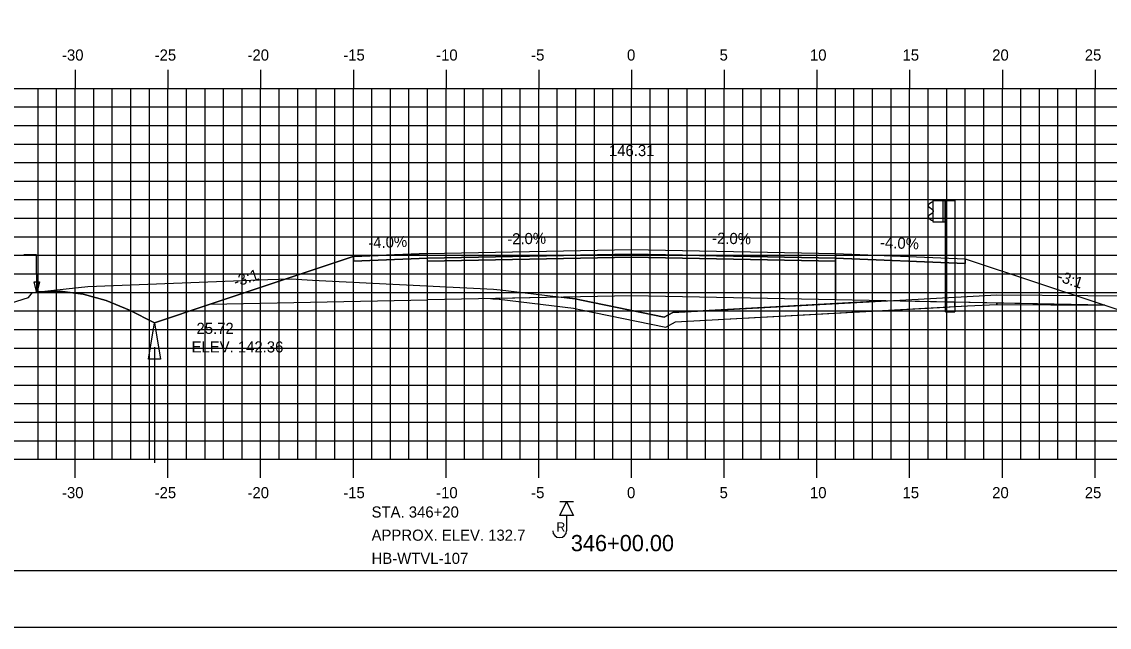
# Model space of a CAD drawing. Extents: x 1143863 to 1144033, y 608981 to 609091.
# Drawn here: x 1143913.7 to 1143972.4, y 608981.3 to 609013.9 of the extents above; entities that cross this region are included whole.
import ezdxf

# ---------------------------------------------------------------- set-up
doc = ezdxf.new("R2010")
doc.units = 0
for name, color, linetype in [('ANNOTATION', 7, 'Continuous'), ('BORDER', 7, 'Continuous'), ('D_Drainage_Ditch_Line', 7, 'Continuous'), ('D_Guardrail_Beam_Rt', 7, 'Continuous'), ('D_Guardrail_ConcBarrier', 7, 'Continuous'), ('D_Roadway_Centerline', 7, 'Continuous'), ('D_Roadway_Centerline_Text', 7, 'Continuous'), ('D_Roadway_Edge_Shoulder', 7, 'Continuous'), ('D_Roadway_Edge_TW', 7, 'Continuous'), ('D_Roadway_Pavement', 7, 'Continuous'), ('D_Roadway_SlopeLines', 7, 'Continuous'), ('D_Roadway_SubGrade', 7, 'Continuous'), ('D_Text_Standard', 7, 'Continuous'), ('H_V ANNOTATION', 7, 'Continuous'), ('MAJOR', 7, 'Continuous'), ('MINOR', 7, 'Continuous'), ('PLOT BOUNDARY', 7, 'Continuous'), ('ROCKS', 7, 'Continuous'), ('S_Roadway_Centerline', 7, 'Continuous'), ('SHADING', 7, 'Continuous')]:
    doc.layers.add(name, color=color, linetype=linetype)

msp = doc.modelspace()

# ---------------------------------------------------------------- linework, layer by layer
msp.add_lwpolyline([(1143914.516, 608999.356), (1143915.766, 608999.394), (1143917.016, 608999.242), (1143918.266, 608998.902), (1143919.516, 608998.371), (1143920.868, 608997.695), (1143923.868, 608998.695), (1143931.592, 609001.27), (1143931.593, 609001.27), (1143935.593, 609001.43), (1143946.593, 609001.65), (1143957.593, 609001.43), (1143964.593, 609001.15), (1143972.125, 608998.639), (1143975.125, 608997.639), (1143975.57, 608997.862), (1143976.82, 608998.408), (1143978.07, 608998.795), (1143979.32, 608999.024), (1143980.57, 608999.095)])
at = {"layer": 'BORDER'}
msp.add_lwpolyline([(1143871.593, 608984.335), (1144031.593, 608984.335), (1144031.593, 609089.335), (1143871.593, 609089.335)], close=True, dxfattribs=at)
at = {"layer": 'D_Drainage_Ditch_Line'}
msp.add_line((1143920.868, 608996.383), (1143920.868, 608990.14), dxfattribs=at)
msp.add_lwpolyline([(1143921.196, 608995.727), (1143920.54, 608995.727), (1143920.868, 608997.695)], close=True, dxfattribs=at)
at = {"layer": 'D_Guardrail_Beam_Rt'}
for p, q in [((1143962.777, 609004.186), (1143962.634, 609004.086)), ((1143962.867, 609004.207), (1143962.793, 609004.193)), ((1143962.634, 609003.943), (1143962.829, 609003.807)), ((1143962.829, 609003.608), (1143962.634, 609003.472)), ((1143962.863, 609003.742), (1143962.863, 609003.672)), ((1143962.634, 609003.329), (1143962.777, 609003.229)), ((1143962.793, 609003.222), (1143962.867, 609003.207))]:
    msp.add_line(p, q, dxfattribs=at)
for centre, major_axis, start_param, end_param in [((1143962.684, 609004.014), (-0.0877, 0), 5.323254, 7.243116), ((1143962.801, 609004.152), (-0.0417, 0), 4.907132, 5.323254), ((1143962.684, 609003.4), (-0.0877, 0), 5.323254, 7.243116), ((1143962.784, 609003.742), (0.0789, 0), 0, 0.959931), ((1143962.784, 609003.672), (0.0789, 0), 5.323254, 6.283185), ((1143962.801, 609003.263), (-0.0417, 0), 0.959931, 1.376053)]:
    msp.add_ellipse(centre, major_axis=major_axis, ratio=0.995501, start_param=start_param, end_param=end_param, dxfattribs=at)
at = {"layer": 'D_Guardrail_ConcBarrier'}
for p, q in [((1143962.867, 609004.291), (1143963.555, 609004.291)), ((1143962.867, 609003.124), (1143962.867, 609004.291)), ((1143963.388, 609004.291), (1143963.388, 609003.124)), ((1143963.492, 609004.291), (1143963.492, 609003.124)), ((1143963.555, 609004.291), (1143964.026, 609004.291)), ((1143963.555, 609004.291), (1143963.555, 609003.124)), ((1143964.026, 609004.291), (1143964.026, 608998.291)), ((1143963.555, 609003.124), (1143962.867, 609003.124)), ((1143963.534, 608998.291), (1143963.534, 609003.124)), ((1143963.534, 608998.291), (1143964.026, 608998.291))]:
    msp.add_line(p, q, dxfattribs=at)
at = {"layer": 'D_Roadway_Edge_Shoulder'}
for points in [[(1143935.593, 609001.43), (1143931.593, 609001.27), (1143931.593, 609001.02), (1143935.593, 609001.18)], [(1143957.593, 609001.43), (1143964.593, 609001.15), (1143964.593, 609000.9), (1143957.593, 609001.18)]]:
    msp.add_lwpolyline(points, close=True, dxfattribs=at)
at = {"layer": 'D_Roadway_Edge_TW'}
msp.add_lwpolyline([(1143935.593, 609001.18), (1143935.593, 609001.43), (1143946.593, 609001.65), (1143957.593, 609001.43), (1143957.593, 609001.18), (1143946.593, 609001.4)], close=True, dxfattribs=at)
at = {"layer": 'D_Roadway_Pavement'}
msp.add_lwpolyline([(1143935.593, 609001.013), (1143935.593, 609001.18), (1143946.593, 609001.4), (1143957.593, 609001.18), (1143957.593, 609001.013), (1143946.593, 609001.233)], close=True, dxfattribs=at)
at = {"layer": 'D_Roadway_SlopeLines'}
for points in [[(1143920.868, 608997.695), (1143919.516, 608998.371), (1143918.266, 608998.902), (1143917.016, 608999.242), (1143915.766, 608999.394), (1143914.516, 608999.356)], [(1143938.984, 608998.998), (1143939.117, 608998.991), (1143939.461, 608998.961), (1143943.464, 608998.476), (1143943.79, 608998.407), (1143948.438, 608997.462), (1143948.971, 608997.739), (1143964.718, 608998.603), (1143966.301, 608998.685), (1143972.122, 608998.64)], [(1143923.868, 608998.695), (1143920.868, 608997.695)], [(1143972.125, 608998.639), (1143975.125, 608997.639)]]:
    msp.add_lwpolyline(points, dxfattribs=at)
at = {"layer": 'D_Roadway_SubGrade'}
for points in [[(1143935.593, 609001.013), (1143935.593, 609001.18), (1143931.593, 609001.02), (1143931.593, 609001.27), (1143931.592, 609001.27), (1143923.868, 608998.695), (1143935.593, 608998.93)], [(1143935.593, 608998.93), (1143935.593, 609001.013), (1143946.593, 609001.233), (1143957.593, 609001.013), (1143957.593, 608998.93), (1143946.593, 608999.15)], [(1143957.593, 609001.013), (1143957.593, 609001.18), (1143964.593, 609000.9), (1143964.593, 609001.15), (1143964.593, 609001.15), (1143972.125, 608998.639), (1143957.593, 608998.93)]]:
    msp.add_lwpolyline(points, close=True, dxfattribs=at)
at = {"layer": 'D_Text_Standard'}
msp.add_lwpolyline([(1143914.522, 608999.315), (1143914.507, 609001.361), (1143913.827, 609001.361)], dxfattribs=at)
msp.add_lwpolyline([(1143914.522, 608999.315), (1143914.372, 608999.896), (1143914.663, 608999.898)], close=True, dxfattribs=at)
at = {"layer": 'MAJOR'}
for p, q in [((1143916.593, 609011.337), (1143916.593, 609010.335)), ((1143921.593, 609011.337), (1143921.593, 609010.335)), ((1143926.593, 609011.337), (1143926.593, 609010.335)), ((1143931.593, 609011.337), (1143931.593, 609010.335)), ((1143936.593, 609011.337), (1143936.593, 609010.335)), ((1143941.593, 609011.337), (1143941.593, 609010.335)), ((1143946.593, 609011.337), (1143946.593, 609010.335)), ((1143951.593, 609011.337), (1143951.593, 609010.335)), ((1143956.593, 609011.337), (1143956.593, 609010.335)), ((1143961.593, 609011.337), (1143961.593, 609010.335)), ((1143966.593, 609011.337), (1143966.593, 609010.335)), ((1143971.593, 609011.337), (1143971.593, 609010.335)), ((1143876.593, 609010.335), (1144016.593, 609010.335)), ((1143876.593, 609010.335), (1144016.593, 609010.335)), ((1143916.593, 608990.335), (1143916.593, 609010.335)), ((1143921.593, 608990.335), (1143921.593, 609010.335)), ((1143926.593, 608990.335), (1143926.593, 609010.335)), ((1143931.593, 608990.335), (1143931.593, 609010.335)), ((1143936.593, 608990.335), (1143936.593, 609010.335)), ((1143941.593, 608990.335), (1143941.593, 609010.335)), ((1143946.593, 608990.335), (1143946.593, 609010.335)), ((1143951.593, 608990.335), (1143951.593, 609010.335)), ((1143956.593, 608990.335), (1143956.593, 609010.335)), ((1143961.593, 608990.335), (1143961.593, 609010.335)), ((1143966.593, 608990.335), (1143966.593, 609010.335)), ((1143971.593, 608990.335), (1143971.593, 609010.335)), ((1143876.593, 609005.335), (1144016.593, 609005.335)), ((1143876.593, 609000.335), (1144016.593, 609000.335)), ((1143876.593, 608995.335), (1144016.593, 608995.335)), ((1143876.593, 608990.335), (1144016.593, 608990.335)), ((1143876.593, 608990.335), (1144016.593, 608990.335)), ((1143916.593, 608989.333), (1143916.593, 608990.335)), ((1143921.593, 608989.333), (1143921.593, 608990.335)), ((1143926.593, 608989.333), (1143926.593, 608990.335)), ((1143931.593, 608989.333), (1143931.593, 608990.335)), ((1143936.593, 608989.333), (1143936.593, 608990.335)), ((1143941.593, 608989.333), (1143941.593, 608990.335)), ((1143946.593, 608989.333), (1143946.593, 608990.335)), ((1143951.593, 608989.333), (1143951.593, 608990.335)), ((1143956.593, 608989.333), (1143956.593, 608990.335)), ((1143961.593, 608989.333), (1143961.593, 608990.335)), ((1143966.593, 608989.333), (1143966.593, 608990.335)), ((1143971.593, 608989.333), (1143971.593, 608990.335))]:
    msp.add_line(p, q, dxfattribs=at)
at = {"layer": 'MINOR'}
for p, q in [((1143914.593, 608990.335), (1143914.593, 609010.335)), ((1143915.593, 608990.335), (1143915.593, 609010.335)), ((1143917.593, 608990.335), (1143917.593, 609010.335)), ((1143918.593, 608990.335), (1143918.593, 609010.335)), ((1143919.593, 608990.335), (1143919.593, 609010.335)), ((1143920.593, 608990.335), (1143920.593, 609010.335)), ((1143922.593, 608990.335), (1143922.593, 609010.335)), ((1143923.593, 608990.335), (1143923.593, 609010.335)), ((1143924.593, 608990.335), (1143924.593, 609010.335)), ((1143925.593, 608990.335), (1143925.593, 609010.335)), ((1143927.593, 608990.335), (1143927.593, 609010.335)), ((1143928.593, 608990.335), (1143928.593, 609010.335)), ((1143929.593, 608990.335), (1143929.593, 609010.335)), ((1143930.593, 608990.335), (1143930.593, 609010.335)), ((1143932.593, 608990.335), (1143932.593, 609010.335)), ((1143933.593, 608990.335), (1143933.593, 609010.335)), ((1143934.593, 608990.335), (1143934.593, 609010.335)), ((1143935.593, 608990.335), (1143935.593, 609010.335)), ((1143937.593, 608990.335), (1143937.593, 609010.335)), ((1143938.593, 608990.335), (1143938.593, 609010.335)), ((1143939.593, 608990.335), (1143939.593, 609010.335)), ((1143940.593, 608990.335), (1143940.593, 609010.335)), ((1143942.593, 608990.335), (1143942.593, 609010.335)), ((1143943.593, 608990.335), (1143943.593, 609010.335)), ((1143944.593, 608990.335), (1143944.593, 609010.335)), ((1143945.593, 608990.335), (1143945.593, 609010.335)), ((1143947.593, 608990.335), (1143947.593, 609010.335)), ((1143948.593, 608990.335), (1143948.593, 609010.335)), ((1143949.593, 608990.335), (1143949.593, 609010.335)), ((1143950.593, 608990.335), (1143950.593, 609010.335)), ((1143952.593, 608990.335), (1143952.593, 609010.335)), ((1143953.593, 608990.335), (1143953.593, 609010.335)), ((1143954.593, 608990.335), (1143954.593, 609010.335)), ((1143955.593, 608990.335), (1143955.593, 609010.335)), ((1143957.593, 608990.335), (1143957.593, 609010.335)), ((1143958.593, 608990.335), (1143958.593, 609010.335)), ((1143959.593, 608990.335), (1143959.593, 609010.335)), ((1143960.593, 608990.335), (1143960.593, 609010.335)), ((1143962.593, 608990.335), (1143962.593, 609010.335)), ((1143963.593, 608990.335), (1143963.593, 609010.335)), ((1143964.593, 608990.335), (1143964.593, 609010.335)), ((1143965.593, 608990.335), (1143965.593, 609010.335)), ((1143967.593, 608990.335), (1143967.593, 609010.335)), ((1143968.593, 608990.335), (1143968.593, 609010.335)), ((1143969.593, 608990.335), (1143969.593, 609010.335)), ((1143970.593, 608990.335), (1143970.593, 609010.335)), ((1143876.593, 609009.335), (1144016.593, 609009.335)), ((1143876.593, 609008.335), (1144016.593, 609008.335)), ((1143876.593, 609007.335), (1144016.593, 609007.335)), ((1143876.593, 609006.335), (1144016.593, 609006.335)), ((1143876.593, 609004.335), (1144016.593, 609004.335)), ((1143876.593, 609003.335), (1144016.593, 609003.335)), ((1143876.593, 609002.335), (1144016.593, 609002.335)), ((1143876.593, 609001.335), (1144016.593, 609001.335)), ((1143876.593, 608999.335), (1144016.593, 608999.335)), ((1143876.593, 608998.335), (1144016.593, 608998.335)), ((1143876.593, 608997.335), (1144016.593, 608997.335)), ((1143876.593, 608996.335), (1144016.593, 608996.335)), ((1143876.593, 608994.335), (1144016.593, 608994.335)), ((1143876.593, 608993.335), (1144016.593, 608993.335)), ((1143876.593, 608992.335), (1144016.593, 608992.335)), ((1143876.593, 608991.335), (1144016.593, 608991.335))]:
    msp.add_line(p, q, dxfattribs=at)
at = {"layer": 'PLOT BOUNDARY'}
msp.add_lwpolyline([(1143863.5, 608981.276), (1144033.5, 608981.276), (1144033.5, 609091.276), (1143863.5, 609091.276)], close=True, dxfattribs=at)
at = {"layer": 'ROCKS'}
for p, q in [((1143943.462, 608988.035), (1143942.724, 608988.035)), ((1143943.093, 608987.297), (1143943.093, 608986.482))]:
    msp.add_line(p, q, dxfattribs=at)
msp.add_lwpolyline([(1143943.093, 608988.035), (1143943.462, 608987.297), (1143942.724, 608987.297)], close=True, dxfattribs=at)
msp.add_arc((1143942.72, 608986.482), 0.373, 180, 0, dxfattribs=at)
at = {"layer": 'S_Roadway_Centerline'}
msp.add_lwpolyline([(1143876.593, 608996.389), (1143886.383, 608996.779), (1143890.479, 608996.962), (1143903.211, 608997.625), (1143906.538, 608998.034), (1143912.067, 608998.435), (1143914.081, 608999.053), (1143914.282, 608999.331), (1143916.775, 608999.597), (1143917.269, 608999.647), (1143926.978, 609000.028), (1143928.239, 609000.064), (1143929.388, 608999.997), (1143939.153, 608999.508), (1143939.515, 608999.476), (1143943.549, 608998.987), (1143943.896, 608998.914), (1143948.361, 608998.006), (1143948.831, 608998.25), (1143964.691, 608999.12), (1143966.29, 608999.203), (1143976.108, 608999.128)], dxfattribs=at)
at = {"layer": 'SHADING'}
for p, q in [((1143942.826, 608999.075), (1143939.46, 608999.007)), ((1143963.534, 608998.811), (1143960.253, 608998.877)), ((1143963.534, 608998.538), (1143963.534, 608998.811)), ((1143964.026, 608998.801), (1143963.534, 608998.811)), ((1143963.534, 608998.811), (1143963.534, 608998.538)), ((1143964.026, 608998.565), (1143964.026, 608998.801)), ((1143966.303, 608998.756), (1143964.026, 608998.801)), ((1143964.026, 608998.801), (1143964.026, 608998.565)), ((1143963.534, 608998.538), (1143964.026, 608998.565)), ((1143964.026, 608998.565), (1143964.718, 608998.603)), ((1143964.718, 608998.603), (1143966.301, 608998.685)), ((1143966.301, 608998.685), (1143972.125, 608998.639)), ((1143972.125, 608998.639), (1143966.303, 608998.756))]:
    msp.add_line(p, q, dxfattribs=at)
for points in [[(1143939.46, 608999.007), (1143939.461, 608998.961)], [(1143939.461, 608998.961), (1143943.464, 608998.476), (1143943.79, 608998.407), (1143948.438, 608997.462), (1143948.971, 608997.739), (1143963.534, 608998.538)], [(1143960.253, 608998.877), (1143948.831, 608998.25), (1143948.361, 608998.006), (1143943.896, 608998.914), (1143943.549, 608998.987), (1143942.826, 608999.075)], [(1143966.301, 608998.685), (1143966.303, 608998.756)], [(1143966.303, 608998.756), (1143966.301, 608998.685)]]:
    msp.add_lwpolyline(points, dxfattribs=at)

# ---------------------------------------------------------------- texts
at = {"layer": 'ANNOTATION'}
for s, rotation, p in [('-4.0%', 2.29061, (1143932.409, 609001.703)), ('-2.0%', 1.14576, (1143939.896, 609001.916)), ('-2.0%', 358.85424, (1143950.936, 609001.963)), ('-4.0%', 357.70939, (1143959.989, 609001.735)), ('-3:1', 18.43482, (1143925.247, 608999.609)), ('-3:1', 341.56522, (1143969.508, 608999.965))]:
    msp.add_text(s, height=0.6, rotation=rotation, dxfattribs=at).set_placement(p)
at = {"layer": 'D_Roadway_Centerline'}
for s, p in [('C', (1143946.587, 609001.65)), ('L', (1143946.593, 609001.643))]:
    msp.add_text(s, height=0.0146, dxfattribs=at).set_placement(p)
at = {"layer": 'D_Roadway_Centerline_Text'}
msp.add_text('146.31', height=0.6, dxfattribs=at).set_placement((1143945.378, 609006.682))
at = {"layer": 'D_Text_Standard'}
for s, p in [('-25.72', (1143922.868, 608997.095)), ('ELEV. 142.36', (1143922.868, 608996.093))]:
    msp.add_text(s, height=0.6, dxfattribs=at).set_placement(p)
at = {"layer": 'H_V ANNOTATION'}
for s, height, p in [('-30', 0.6, (1143915.881, 609011.835)), ('-25', 0.6, (1143920.878, 609011.835)), ('-20', 0.6, (1143925.886, 609011.835)), ('-15', 0.6, (1143931.05, 609011.835)), ('-10', 0.6, (1143936.058, 609011.835)), ('-5', 0.6, (1143941.183, 609011.835)), ('0', 0.6, (1143946.352, 609011.835)), ('5', 0.6, (1143951.344, 609011.835)), ('10', 0.6, (1143956.218, 609011.835)), ('15', 0.6, (1143961.21, 609011.835)), ('20', 0.6, (1143966.047, 609011.835)), ('25', 0.6, (1143971.039, 609011.835)), ('-30', 0.6, (1143915.881, 608988.235)), ('-25', 0.6, (1143920.878, 608988.235)), ('-20', 0.6, (1143925.886, 608988.235)), ('-15', 0.6, (1143931.05, 608988.235)), ('-10', 0.6, (1143936.058, 608988.235)), ('-5', 0.6, (1143941.183, 608988.235)), ('0', 0.6, (1143946.352, 608988.235)), ('5', 0.6, (1143951.344, 608988.235)), ('10', 0.6, (1143956.218, 608988.235)), ('15', 0.6, (1143961.21, 608988.235)), ('20', 0.6, (1143966.047, 608988.235)), ('25', 0.6, (1143971.039, 608988.235)), ('346+00.00', 0.875, (1143943.323, 608985.378))]:
    msp.add_text(s, height=height, dxfattribs=at).set_placement(p)
at = {"layer": 'ROCKS'}
for s, p in [('STA. 346+20', (1143932.577, 608987.191)), ('APPROX. ELEV. 132.7', (1143932.577, 608985.941)), ('HB-WTVL-107', (1143932.577, 608984.691))]:
    msp.add_text(s, height=0.6, rotation=360, dxfattribs=at).set_placement(p)
msp.add_text('R', height=0.492, dxfattribs=at).set_placement((1143942.547, 608986.439))
at = {"layer": 'S_Roadway_Centerline'}
for s, p in [('L', (1143928.23, 609000.057)), ('C', (1143928.234, 609000.064))]:
    msp.add_text(s, height=0.0146, dxfattribs=at).set_placement(p)

doc.saveas('drawing.dxf')
